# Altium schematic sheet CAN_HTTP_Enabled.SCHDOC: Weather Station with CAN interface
size C; Organization: Altium Limited; Address1: L3, 12a Rodborough Rd; Address2: Frenchs Forest; Address3: NSW; Address4: Australia 2086; DocumentNumber: 1; SheetNumber: 1; SheetTotal: 2
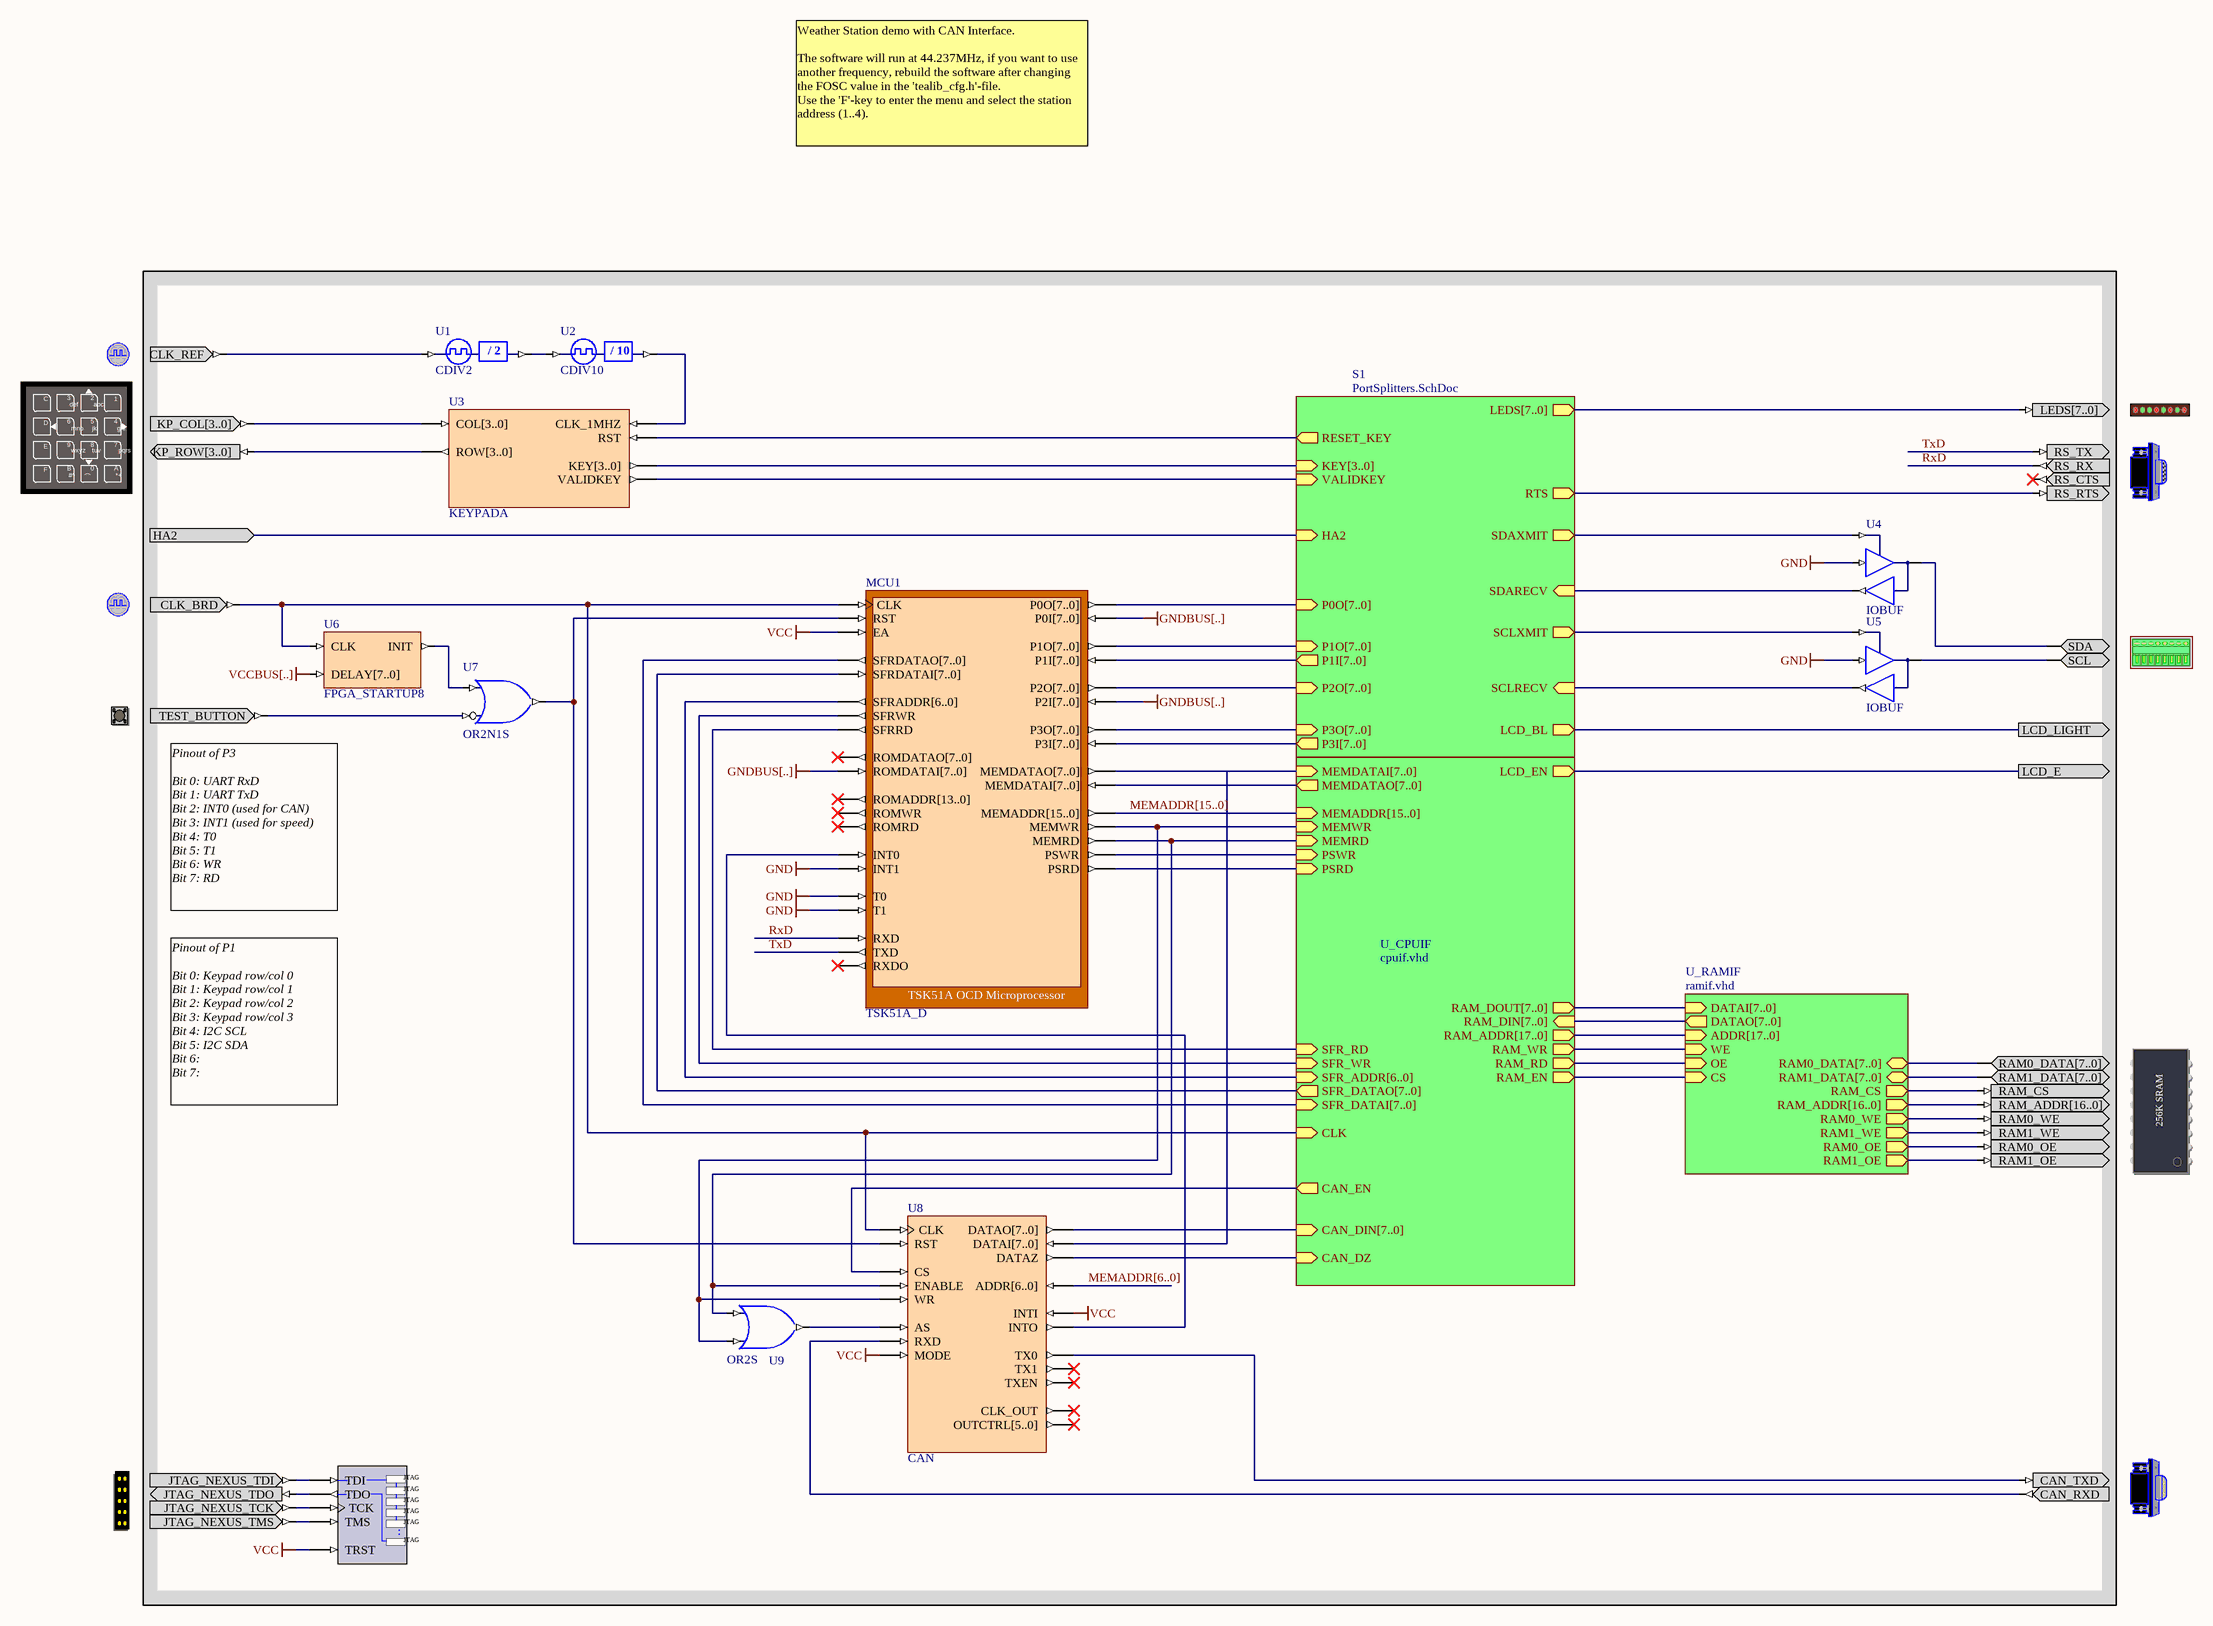
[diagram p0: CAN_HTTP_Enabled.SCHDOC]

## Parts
(Parts that share a designator on the sheet are numbered #1, #2 ... from top to bottom, then left to right.)
?#1  CLOCK_REFERENCE  (value not drawn)
?#2  KEYPAD  (value not drawn)
?#3  LED  (value not drawn)
?#4  RS232CNTR  (value not drawn)
?#5  CLOCK_BOARD  (value not drawn)
?#6  ADCDAC_I2C  (value not drawn)
?#7  TEST_BUTTON  (value not drawn)
?#8  MEMORY256KX8  (value not drawn)
?#9  CANCNTR  (value not drawn)
?#10  NEXUS_JTAG_CONNECTOR  (value not drawn)
MCU1  TSK51A_D
NEXUS_JTAG_PORT  NEXUS_JTAG_PORT  (value not drawn)
U1  CDIV2
U2  CDIV10
U3  KEYPADA
U4  IOBUF
U5  IOBUF
U6  FPGA_STARTUP8
U7  OR2N1S
U8  CAN
U9  OR2S

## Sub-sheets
S1 = PortSplitters.SchDoc: P0O[7..0] (in), P1O[7..0] (in), P1I[7..0] (out), P2O[7..0] (in), P3O[7..0] (in), P3I[7..0] (out), HA2 (in), SCLXMIT (out), LCD_BL (out), RTS (out), SDAXMIT (out), VALIDKEY (in), KEY[3..0] (in), SCLRECV (in), SDARECV (in), RESET_KEY (out), LEDS[7..0] (out)
U_CPUIF = cpuif.vhd: MEMWR (in), RAM_EN (out), RAM_WR (out), RAM_RD (out), RAM_DOUT[7..0] (out), MEMRD (in), LCD_EN (out), RAM_ADDR[17..0] (out), CLK (in), SFR_ADDR[6..0] (in), SFR_DATAI[7..0] (in), SFR_DATAO[7..0] (out), SFR_WR (in), SFR_RD (in), RAM_DIN[7..0] (in), PSWR (in), PSRD (in), MEMADDR[15..0] (in), MEMDATAI[7..0] (in), MEMDATAO[7..0] (out), CAN_EN (out), CAN_DIN[7..0] (in), CAN_DZ (in)
U_RAMIF = ramif.vhd: DATAI[7..0] (in), DATAO[7..0] (out), ADDR[17..0] (in), WE (in), OE (in), CS (in), RAM0_DATA[7..0] (bidir), RAM1_DATA[7..0] (bidir), RAM_ADDR[16..0] (out), RAM0_WE (out), RAM1_WE (out), RAM0_OE (out), RAM1_OE (out), RAM_CS (out)

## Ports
HA2 (in), LCD_E (out), LCD_LIGHT (out)

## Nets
GND: MCU1.INT1 MCU1.T0 MCU1.T1 U4.I U5.I
VCC: MCU1.EA NEXUS_JTAG_PORT.TRST U8.INTI U8.MODE
VCCBUS[..]: U6.DELAY[7..0]
HA2: port HA2, sheet S1/HA2
LCD_E: port LCD_E, sheet U_CPUIF/LCD_EN
LCD_LIGHT: port LCD_LIGHT, sheet S1/LCD_BL
RxD: ?#4.RS_RX MCU1.RXD
TxD: ?#4.RS_TX MCU1.TXD
Net?#1_CLK_REF: ?#1.CLK_REF U1.CLKIN
Net?#4_RS_RTS: ?#4.RS_RTS ; sheet S1/RTS
Net?#5_CLK_BRD: ?#5.CLK_BRD MCU1.CLK U6.CLK U8.CLK ; sheet U_CPUIF/CLK
Net?#6_SCL: ?#6.SCL U5.IO
Net?#6_SDA: ?#6.SDA U4.IO
Net?#7_TEST_BUTTON: ?#7.TEST_BUTTON U7.I0
Net?#8_RAM0_OE: ?#8.RAM0_OE ; sheet U_RAMIF/RAM0_OE
Net?#8_RAM0_WE: ?#8.RAM0_WE ; sheet U_RAMIF/RAM0_WE
Net?#8_RAM1_OE: ?#8.RAM1_OE ; sheet U_RAMIF/RAM1_OE
Net?#8_RAM1_WE: ?#8.RAM1_WE ; sheet U_RAMIF/RAM1_WE
Net?#8_RAM_CS: ?#8.RAM_CS ; sheet U_RAMIF/RAM_CS
Net?#9_CAN_RXD: ?#9.CAN_RXD U8.RXD
Net?#9_CAN_TXD: ?#9.CAN_TXD U8.TX0
Net?#10_JTAG_NEXUS_TCK: ?#10.JTAG_NEXUS_TCK NEXUS_JTAG_PORT.TCK
Net?#10_JTAG_NEXUS_TDI: ?#10.JTAG_NEXUS_TDI NEXUS_JTAG_PORT.TDI
Net?#10_JTAG_NEXUS_TDO: ?#10.JTAG_NEXUS_TDO NEXUS_JTAG_PORT.TDO
Net?#10_JTAG_NEXUS_TMS: ?#10.JTAG_NEXUS_TMS NEXUS_JTAG_PORT.TMS
NetMCU1_INT0: MCU1.INT0 U8.INTO
NetMCU1_MEMRD: MCU1.MEMRD U8.ENABLE U9.I0 ; sheet U_CPUIF/MEMRD
NetMCU1_MEMWR: MCU1.MEMWR U8.WR U9.I1 ; sheet U_CPUIF/MEMWR
NetMCU1_PSRD: MCU1.PSRD ; sheet U_CPUIF/PSRD
NetMCU1_PSWR: MCU1.PSWR ; sheet U_CPUIF/PSWR
NetMCU1_RST: MCU1.RST U7.O U8.RST
NetMCU1_SFRRD: MCU1.SFRRD ; sheet U_CPUIF/SFR_RD
NetMCU1_SFRWR: MCU1.SFRWR ; sheet U_CPUIF/SFR_WR
NetU1_CLKDV: U1.CLKDV U2.CLKIN
NetU2_CLKDV: U2.CLKDV U3.CLK_1MHZ
NetU3_RST: U3.RST ; sheet S1/RESET_KEY
NetU3_VALIDKEY: U3.VALIDKEY ; sheet S1/VALIDKEY
NetU4_O: U4.O ; sheet S1/SDARECV
NetU4_T: U4.T ; sheet S1/SDAXMIT
NetU5_O: U5.O ; sheet S1/SCLRECV
NetU5_T: U5.T ; sheet S1/SCLXMIT
NetU6_INIT: U6.INIT U7.I1
NetU8_AS: U8.AS U9.O
NetU8_CS: U8.CS ; sheet U_CPUIF/CAN_EN
NetU8_DATAZ: U8.DATAZ ; sheet U_CPUIF/CAN_DZ
(unnamed): sheet U_CPUIF/RAM_EN, sheet U_RAMIF/CS
(unnamed): sheet U_CPUIF/RAM_WR, sheet U_RAMIF/WE  [a separate net that carries the same name]
(unnamed): sheet U_CPUIF/RAM_RD, sheet U_RAMIF/OE  [a separate net that carries the same name]

Not connected (* = marked no-connect by the designer): ?#2 KP_COL[3..0] KP_ROW[3..0]; ?#3 LEDS[7..0]; ?#4 RS_CTS*; ?#8 RAM0_DATA[7..0] RAM1_DATA[7..0] RAM_ADDR[16..0]; MCU1 MEMADDR[15..0] MEMDATAI[7..0] MEMDATAO[7..0] P0I[7..0] P0O[7..0] P1I[7..0] P1O[7..0] P2I[7..0] P2O[7..0] P3I[7..0] P3O[7..0] ROMADDR[13..0]* ROMDATAI[7..0] ROMDATAO[7..0]* ROMRD* ROMWR* RXDO* SFRADDR[6..0] SFRDATAI[7..0] SFRDATAO[7..0]; U3 COL[3..0] KEY[3..0] ROW[3..0]; U8 ADDR[6..0] CLK_OUT* DATAI[7..0] DATAO[7..0] OUTCTRL[5..0]* TX1* TXEN*

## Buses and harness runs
bus MEMADDR[6..0]
bus MEMADDR[15..0] = sheet U_CPUIF/MEMADDR[15..0]
bus sheet U_CPUIF/RAM_ADDR[17..0] = sheet U_RAMIF/ADDR[17..0]
bus sheet U_CPUIF/RAM_DIN[7..0] = sheet U_RAMIF/DATAO[7..0]
bus sheet U_CPUIF/RAM_DOUT[7..0] = sheet U_RAMIF/DATAI[7..0]

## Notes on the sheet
- Weather Station demo with CAN Interface.
  The software will run at 44.237MHz, if you want to use another frequency, rebuild the software after changing the FOSC value in the 'tealib_cfg.h'-file.
  Use the 'F'-key to enter the menu and select the station address (1..4).
- Pinout of P3
  Bit 0: UART RxD
  Bit 1: UART TxD
  Bit 2: INT0 (used for CAN)
  Bit 3: INT1 (used for speed)
  Bit 4: T0
  Bit 5: T1
  Bit 6: WR
  Bit 7: RD
- Pinout of P1
  Bit 0: Keypad row/col 0
  Bit 1: Keypad row/col 1
  Bit 2: Keypad row/col 2
  Bit 3: Keypad row/col 3
  Bit 4: I2C SCL
  Bit 5: I2C SDA
  Bit 6:
  Bit 7:
- Labels drawn without touching a wire or pin: GNDBUS[..]

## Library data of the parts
?#1 = CLOCK_REFERENCE: Global System Clock Reference Supply; PortComponent: True
?#2 = KEYPAD: Key Pad; PortComponent: True
?#3 = LED: 8-Way LEDS; PortComponent: True
?#4 = RS232CNTR: DCE Serial Port Connector; PortComponent: True
?#5 = CLOCK_BOARD: Global System Clock Supply; PortComponent: True
?#6 = ADCDAC_I2C: Analog Digital/ Digital Analog Converter, I2C Interface; PortComponent: True
?#7 = TEST_BUTTON: Test Button; PortComponent: True
?#8 = MEMORY256KX8: SRAM 256kx8; PortComponent: True
?#9 = CANCNTR: CAN Bus Connector; PortComponent: True
?#10 = NEXUS_JTAG_CONNECTOR: JTAG Port; PortComponent: True
MCU1 = TSK51A_D: TSK51A OCD Microprocessor; NEXUS_CORE: Processor_OCDS; NEXUS_JTAG_DEVICE: True; NEXUS_JTAG_ORDER: 0; ChildModel1: RAM256x8_TSK51D
NEXUS_JTAG_PORT = NEXUS_JTAG_PORT: Nexus Processor JTAG Chain Connector; NEXUS_JTAG_CONNECTOR: True
U1 = CDIV2: Clock Divider by 2; ArchiveName: GENERIC
U2 = CDIV10: Clock Divider by 10; ArchiveName: GENERIC
U3 = KEYPADA: Keypad
U4 U5 = IOBUF: Input/Output Buffer; ArchiveName: GENERIC
U6 = FPGA_STARTUP8: FPGA Startup With 8 Bit Delay
U7 = OR2N1S: 2-Input OR Gate with Active Low A Input, Single Pin Version; Xilinx Equivalent: OR2B1; ArchiveName: GENERIC
U8 = CAN: CAN Controller; ChildModel1: CAN10000_DRAM8X64
U9 = OR2S: 2-Input OR Gate, Single Pin Version; Xilinx Equivalent: OR2; ArchiveName: GENERIC; VHDLIB_SIM: GENERIC_LIB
